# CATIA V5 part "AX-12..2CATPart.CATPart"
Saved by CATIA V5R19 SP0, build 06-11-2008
Part number: DX124_DUMMY
Revision: 27
Definition: design
Nomenclature: DX124_DUMMY
Source: made
Description: NOT SPECIFIED
Bounding box of the stored display mesh (mm): x -16 to 16, y -38.5 to 11.5, z -19 to 19
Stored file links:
  I:\mediator\AX-12..2CATPart.CATPart
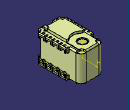
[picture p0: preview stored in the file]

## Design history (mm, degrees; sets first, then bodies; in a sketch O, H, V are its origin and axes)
Set1
  DatumSurface1 "CURVE_BOUNDED_SURFACE #7207"
  DatumSurface2 "CURVE_BOUNDED_SURFACE #7250"
  DatumSurface3 "CURVE_BOUNDED_SURFACE #7292"
  DatumSurface4 "CURVE_BOUNDED_SURFACE #7334"
  DatumSurface5 "CURVE_BOUNDED_SURFACE #7375"
  DatumSurface6 "CURVE_BOUNDED_SURFACE #7451"
  DatumSurface7 "CURVE_BOUNDED_SURFACE #7526"
  DatumSurface8 "CURVE_BOUNDED_SURFACE #7737"
  DatumSurface9 "CURVE_BOUNDED_SURFACE #7833"
  DatumSurface10 "CURVE_BOUNDED_SURFACE #7875"
  DatumSurface11 "CURVE_BOUNDED_SURFACE #7970"
  DatumSurface12 "CURVE_BOUNDED_SURFACE #8046"
  DatumSurface13 "CURVE_BOUNDED_SURFACE #8088"
  DatumSurface14 "CURVE_BOUNDED_SURFACE #8129"
  DatumSurface15 "CURVE_BOUNDED_SURFACE #8204"
  DatumSurface16 "CURVE_BOUNDED_SURFACE #8245"
  DatumSurface17 "CURVE_BOUNDED_SURFACE #8286"
  DatumSurface18 "CURVE_BOUNDED_SURFACE #8361"
  DatumSurface19 "CURVE_BOUNDED_SURFACE #9345"
  DatumSurface20 "CURVE_BOUNDED_SURFACE #9397"
  DatumSurface21 "CURVE_BOUNDED_SURFACE #9488"
  DatumSurface22 "CURVE_BOUNDED_SURFACE #9579"
  DatumSurface23 "CURVE_BOUNDED_SURFACE #9670"
  DatumSurface24 "CURVE_BOUNDED_SURFACE #9761"
  DatumSurface25 "CURVE_BOUNDED_SURFACE #9851"
  DatumSurface26 "CURVE_BOUNDED_SURFACE #9929"
  DatumSurface27 "CURVE_BOUNDED_SURFACE #10008"
  DatumSurface28 "CURVE_BOUNDED_SURFACE #10058"
  DatumSurface29 "CURVE_BOUNDED_SURFACE #10131"
  DatumSurface30 "CURVE_BOUNDED_SURFACE #10210"
  DatumSurface31 "CURVE_BOUNDED_SURFACE #10289"
  DatumSurface32 "CURVE_BOUNDED_SURFACE #10368"
  DatumSurface33 "CURVE_BOUNDED_SURFACE #10429"
  DatumSurface34 "CURVE_BOUNDED_SURFACE #10500"
  DatumSurface35 "CURVE_BOUNDED_SURFACE #10573"
  DatumSurface36 "CURVE_BOUNDED_SURFACE #10652"
  DatumSurface37 "CURVE_BOUNDED_SURFACE #10731"
  DatumSurface38 "CURVE_BOUNDED_SURFACE #10810"
  DatumSurface39 "CURVE_BOUNDED_SURFACE #10871"
  DatumSurface40 "CURVE_BOUNDED_SURFACE #10943"
  DatumSurface41 "CURVE_BOUNDED_SURFACE #10985"
  DatumSurface42 "CURVE_BOUNDED_SURFACE #11027"
  DatumSurface43 "CURVE_BOUNDED_SURFACE #11077"
  DatumSurface44 "CURVE_BOUNDED_SURFACE #11153"
  DatumSurface45 "CURVE_BOUNDED_SURFACE #11230"
  DatumSurface46 "CURVE_BOUNDED_SURFACE #11307"
  DatumSurface47 "CURVE_BOUNDED_SURFACE #11384"
  DatumSurface48 "CURVE_BOUNDED_SURFACE #11460"
  DatumSurface49 "CURVE_BOUNDED_SURFACE #11958"
  DatumSurface50 "CURVE_BOUNDED_SURFACE #12121"
  DatumSurface51 "CURVE_BOUNDED_SURFACE #12250"
  DatumSurface52 "CURVE_BOUNDED_SURFACE #12382"
  DatumSurface53 "CURVE_BOUNDED_SURFACE #12492"
  DatumSurface54 "CURVE_BOUNDED_SURFACE #12532"
  DatumSurface55 "CURVE_BOUNDED_SURFACE #12571"
  DatumSurface56 "CURVE_BOUNDED_SURFACE #12683"
  DatumSurface57 "CURVE_BOUNDED_SURFACE #12743"
  DatumSurface58 "CURVE_BOUNDED_SURFACE #12800"
  DatumSurface59 "CURVE_BOUNDED_SURFACE #12871"
  DatumSurface60 "CURVE_BOUNDED_SURFACE #12949"
  DatumSurface61 "CURVE_BOUNDED_SURFACE #13027"
  DatumSurface62 "CURVE_BOUNDED_SURFACE #13105"
  DatumSurface63 "CURVE_BOUNDED_SURFACE #13165"
  DatumSurface64 "CURVE_BOUNDED_SURFACE #13236"
  DatumSurface65 "CURVE_BOUNDED_SURFACE #13309"
  DatumSurface66 "CURVE_BOUNDED_SURFACE #13388"
  DatumSurface67 "CURVE_BOUNDED_SURFACE #13467"
  DatumSurface68 "CURVE_BOUNDED_SURFACE #13546"
  DatumSurface69 "CURVE_BOUNDED_SURFACE #13607"
  DatumSurface70 "CURVE_BOUNDED_SURFACE #13679"
  DatumSurface71 "CURVE_BOUNDED_SURFACE #13721"
  DatumSurface72 "CURVE_BOUNDED_SURFACE #13761"
  DatumSurface73 "CURVE_BOUNDED_SURFACE #13812"
  DatumSurface74 "CURVE_BOUNDED_SURFACE #13888"
  DatumSurface75 "CURVE_BOUNDED_SURFACE #13965"
  DatumSurface76 "CURVE_BOUNDED_SURFACE #14042"
  DatumSurface77 "CURVE_BOUNDED_SURFACE #14119"
  DatumSurface78 "CURVE_BOUNDED_SURFACE #14208"
  DatumSurface79 "CURVE_BOUNDED_SURFACE #14298"
  DatumSurface80 "CURVE_BOUNDED_SURFACE #14388"
  DatumSurface81 "CURVE_BOUNDED_SURFACE #14478"
  DatumSurface82 "CURVE_BOUNDED_SURFACE #14568"
  DatumSurface83 "CURVE_BOUNDED_SURFACE #14617"
  DatumSurface84 "CURVE_BOUNDED_SURFACE #14690"
  DatumSurface85 "CURVE_BOUNDED_SURFACE #14765"
  DatumSurface86 "CURVE_BOUNDED_SURFACE #14840"
  DatumSurface87 "CURVE_BOUNDED_SURFACE #14915"
  DatumSurface88 "CURVE_BOUNDED_SURFACE #14989"
  DatumSurface89 "CURVE_BOUNDED_SURFACE #15029"
  DatumSurface90 "CURVE_BOUNDED_SURFACE #15068"
  DatumSurface91 "CURVE_BOUNDED_SURFACE #15118"
  DatumSurface92 "CURVE_BOUNDED_SURFACE #15170"
  DatumSurface93 "CURVE_BOUNDED_SURFACE #15199"
  DatumSurface94 "CURVE_BOUNDED_SURFACE #15229"
  DatumSurface95 "CURVE_BOUNDED_SURFACE #15259"
  DatumSurface96 "CURVE_BOUNDED_SURFACE #15289"
  DatumSurface97 "CURVE_BOUNDED_SURFACE #15320"
  DatumSurface98 "CURVE_BOUNDED_SURFACE #15369"
  DatumSurface99 "CURVE_BOUNDED_SURFACE #15421"
  DatumSurface100 "CURVE_BOUNDED_SURFACE #15471"
  DatumSurface101 "CURVE_BOUNDED_SURFACE #16436"
  DatumSurface102 "CURVE_BOUNDED_SURFACE #16487"
  DatumSurface103 "CURVE_BOUNDED_SURFACE #16536"
  DatumSurface104 "CURVE_BOUNDED_SURFACE #16585"
  DatumSurface105 "CURVE_BOUNDED_SURFACE #16636"
  DatumSurface106 "CURVE_BOUNDED_SURFACE #16685"
  DatumSurface107 "CURVE_BOUNDED_SURFACE #16734"
  DatumSurface108 "CURVE_BOUNDED_SURFACE #16783"
  DatumSurface109 "CURVE_BOUNDED_SURFACE #16834"
  DatumSurface110 "CURVE_BOUNDED_SURFACE #16887"
  DatumSurface111 "CURVE_BOUNDED_SURFACE #16940"
  DatumSurface112 "CURVE_BOUNDED_SURFACE #16992"
  DatumSurface113 "CURVE_BOUNDED_SURFACE #17083"
  DatumSurface114 "CURVE_BOUNDED_SURFACE #17174"
  DatumSurface115 "CURVE_BOUNDED_SURFACE #17265"
  DatumSurface116 "CURVE_BOUNDED_SURFACE #17355"
  DatumSurface117 "CURVE_BOUNDED_SURFACE #17446"
  DatumSurface118 "CURVE_BOUNDED_SURFACE #17522"
  DatumSurface119 "CURVE_BOUNDED_SURFACE #17598"
  DatumSurface120 "CURVE_BOUNDED_SURFACE #17674"
  DatumSurface121 "CURVE_BOUNDED_SURFACE #17750"
  DatumSurface122 "CURVE_BOUNDED_SURFACE #17799"
  DatumSurface123 "CURVE_BOUNDED_SURFACE #17840"
  DatumSurface124 "CURVE_BOUNDED_SURFACE #17915"
  DatumSurface125 "CURVE_BOUNDED_SURFACE #17992"
  DatumSurface126 "CURVE_BOUNDED_SURFACE #18069"
  DatumSurface127 "CURVE_BOUNDED_SURFACE #18146"
  DatumSurface128 "CURVE_BOUNDED_SURFACE #18221"
  DatumSurface129 "CURVE_BOUNDED_SURFACE #18714"
  DatumSurface130 "CURVE_BOUNDED_SURFACE #18789"
  DatumSurface131 "CURVE_BOUNDED_SURFACE #18864"
  DatumSurface132 "CURVE_BOUNDED_SURFACE #18939"
  DatumSurface133 "CURVE_BOUNDED_SURFACE #19014"
  DatumSurface134 "CURVE_BOUNDED_SURFACE #19089"
  DatumSurface135 "CURVE_BOUNDED_SURFACE #19139"
  DatumSurface136 "CURVE_BOUNDED_SURFACE #19215"
  DatumSurface137 "CURVE_BOUNDED_SURFACE #19292"
  DatumSurface138 "CURVE_BOUNDED_SURFACE #19369"
  DatumSurface139 "CURVE_BOUNDED_SURFACE #19446"
  DatumSurface140 "CURVE_BOUNDED_SURFACE #19536"
  DatumSurface141 "CURVE_BOUNDED_SURFACE #19625"
  DatumSurface142 "CURVE_BOUNDED_SURFACE #19715"
  DatumSurface143 "CURVE_BOUNDED_SURFACE #19805"
  DatumSurface144 "CURVE_BOUNDED_SURFACE #19895"
  DatumSurface145 "CURVE_BOUNDED_SURFACE #19943"
  DatumSurface146 "CURVE_BOUNDED_SURFACE #19983"
  DatumSurface147 "CURVE_BOUNDED_SURFACE #20023"
  DatumSurface148 "CURVE_BOUNDED_SURFACE #20128"
  DatumSurface149 "CURVE_BOUNDED_SURFACE #20168"
  DatumSurface150 "CURVE_BOUNDED_SURFACE #20208"
  DatumSurface151 "CURVE_BOUNDED_SURFACE #20256"
  DatumSurface152 "CURVE_BOUNDED_SURFACE #20330"
  DatumSurface153 "CURVE_BOUNDED_SURFACE #20404"
  DatumSurface154 "CURVE_BOUNDED_SURFACE #20444"
  DatumSurface155 "CURVE_BOUNDED_SURFACE #20502"
  DatumSurface156 "CURVE_BOUNDED_SURFACE #20559"
  DatumSurface157 "CURVE_BOUNDED_SURFACE #20598"
  DatumSurface158 "CURVE_BOUNDED_SURFACE #20639"
  DatumSurface159 "CURVE_BOUNDED_SURFACE #20680"
  DatumSurface160 "CURVE_BOUNDED_SURFACE #20730"
  DatumSurface161 "CURVE_BOUNDED_SURFACE #20769"
  DatumSurface162 "CURVE_BOUNDED_SURFACE #20819"
  DatumSurface163 "CURVE_BOUNDED_SURFACE #20858"
  DatumSurface164 "CURVE_BOUNDED_SURFACE #20906"
  DatumSurface165 "CURVE_BOUNDED_SURFACE #20946"
  DatumSurface166 "CURVE_BOUNDED_SURFACE #20985"
  DatumSurface167 "CURVE_BOUNDED_SURFACE #21043"
  DatumSurface168 "CURVE_BOUNDED_SURFACE #21101"
  DatumSurface169 "CURVE_BOUNDED_SURFACE #21153"
  DatumSurface170 "CURVE_BOUNDED_SURFACE #21311"
  DatumSurface171 "CURVE_BOUNDED_SURFACE #21352"
  DatumSurface172 "CURVE_BOUNDED_SURFACE #21394"
  DatumSurface173 "CURVE_BOUNDED_SURFACE #21435"
  DatumSurface174 "CURVE_BOUNDED_SURFACE #21486"
  DatumSurface175 "CURVE_BOUNDED_SURFACE #21542"
  DatumSurface176 "CURVE_BOUNDED_SURFACE #21599"
  DatumSurface177 "CURVE_BOUNDED_SURFACE #21639"
  DatumSurface178 "CURVE_BOUNDED_SURFACE #21696"
  DatumSurface179 "CURVE_BOUNDED_SURFACE #21754"
  DatumSurface180 "CURVE_BOUNDED_SURFACE #21795"
  DatumSurface181 "CURVE_BOUNDED_SURFACE #21852"
  DatumSurface182 "CURVE_BOUNDED_SURFACE #21910"
  DatumSurface183 "CURVE_BOUNDED_SURFACE #21950"
  DatumSurface184 "CURVE_BOUNDED_SURFACE #22007"
  DatumSurface185 "CURVE_BOUNDED_SURFACE #22065"
  DatumSurface186 "CURVE_BOUNDED_SURFACE #22106"
  DatumSurface187 "CURVE_BOUNDED_SURFACE #22163"
  DatumSurface188 "CURVE_BOUNDED_SURFACE #22221"
  DatumSurface189 "CURVE_BOUNDED_SURFACE #22261"
  DatumSurface190 "CURVE_BOUNDED_SURFACE #22318"
  DatumSurface191 "CURVE_BOUNDED_SURFACE #22376"
  DatumSurface192 "CURVE_BOUNDED_SURFACE #22417"
  DatumSurface193 "CURVE_BOUNDED_SURFACE #22474"
  DatumSurface194 "CURVE_BOUNDED_SURFACE #22532"
  DatumSurface195 "CURVE_BOUNDED_SURFACE #22572"
  DatumSurface196 "CURVE_BOUNDED_SURFACE #22630"
  DatumSurface197 "CURVE_BOUNDED_SURFACE #22689"
  DatumSurface198 "CURVE_BOUNDED_SURFACE #22746"
  DatumSurface199 "CURVE_BOUNDED_SURFACE #22804"
  DatumSurface200 "CURVE_BOUNDED_SURFACE #22845"
  DatumSurface201 "CURVE_BOUNDED_SURFACE #22907"
  DatumSurface202 "CURVE_BOUNDED_SURFACE #22955"
  DatumSurface203 "CURVE_BOUNDED_SURFACE #23044"
  DatumSurface204 "CURVE_BOUNDED_SURFACE #23111"
  DatumSurface205 "CURVE_BOUNDED_SURFACE #23158"
  DatumSurface206 "CURVE_BOUNDED_SURFACE #23205"
  DatumSurface207 "CURVE_BOUNDED_SURFACE #23259"
  DatumSurface208 "CURVE_BOUNDED_SURFACE #23314"
  DatumSurface209 "CURVE_BOUNDED_SURFACE #23383"
  DatumSurface210 "CURVE_BOUNDED_SURFACE #23505"
  DatumSurface211 "CURVE_BOUNDED_SURFACE #23547"
  DatumSurface212 "CURVE_BOUNDED_SURFACE #23589"
  DatumSurface213 "CURVE_BOUNDED_SURFACE #23647"
  DatumSurface214 "CURVE_BOUNDED_SURFACE #23827"
  DatumSurface215 "CURVE_BOUNDED_SURFACE #23877"
  DatumSurface216 "CURVE_BOUNDED_SURFACE #23932"
  DatumSurface217 "CURVE_BOUNDED_SURFACE #23980"
  DatumSurface218 "CURVE_BOUNDED_SURFACE #24042"
  DatumSurface219 "CURVE_BOUNDED_SURFACE #24131"
  DatumSurface220 "CURVE_BOUNDED_SURFACE #24179"
  DatumSurface221 "CURVE_BOUNDED_SURFACE #24241"
  DatumSurface222 "CURVE_BOUNDED_SURFACE #24281"
  DatumSurface223 "CURVE_BOUNDED_SURFACE #24322"
  DatumSurface224 "CURVE_BOUNDED_SURFACE #24361"
  DatumSurface225 "CURVE_BOUNDED_SURFACE #24401"
  DatumSurface226 "CURVE_BOUNDED_SURFACE #24462"
  DatumSurface227 "CURVE_BOUNDED_SURFACE #24510"
  DatumSurface228 "CURVE_BOUNDED_SURFACE #24595"
  DatumSurface229 "CURVE_BOUNDED_SURFACE #24660"
  DatumSurface230 "CURVE_BOUNDED_SURFACE #24717"
  DatumSurface231 "CURVE_BOUNDED_SURFACE #24765"
  DatumSurface232 "CURVE_BOUNDED_SURFACE #24849"
  DatumSurface233 "CURVE_BOUNDED_SURFACE #24897"
  DatumSurface234 "CURVE_BOUNDED_SURFACE #24959"
  DatumSurface235 "CURVE_BOUNDED_SURFACE #24999"
  DatumSurface236 "CURVE_BOUNDED_SURFACE #25038"
  DatumSurface237 "CURVE_BOUNDED_SURFACE #25077"
  DatumSurface238 "CURVE_BOUNDED_SURFACE #25131"
  DatumSurface239 "CURVE_BOUNDED_SURFACE #25179"
  DatumSurface240 "CURVE_BOUNDED_SURFACE #25241"
  DatumSurface241 "CURVE_BOUNDED_SURFACE #25296"
  DatumSurface242 "CURVE_BOUNDED_SURFACE #25343"
  DatumSurface243 "CURVE_BOUNDED_SURFACE #27073"
  DatumSurface244 "CURVE_BOUNDED_SURFACE #27139"
  DatumSurface245 "CURVE_BOUNDED_SURFACE #27179"
  DatumSurface246 "CURVE_BOUNDED_SURFACE #27244"
  DatumSurface247 "CURVE_BOUNDED_SURFACE #27284"
  DatumSurface248 "CURVE_BOUNDED_SURFACE #27343"
  DatumSurface249 "CURVE_BOUNDED_SURFACE #27400"
  DatumSurface250 "CURVE_BOUNDED_SURFACE #27441"
  DatumSurface251 "CURVE_BOUNDED_SURFACE #27499"
  DatumSurface252 "CURVE_BOUNDED_SURFACE #27557"
  DatumSurface253 "CURVE_BOUNDED_SURFACE #27598"
  DatumSurface254 "CURVE_BOUNDED_SURFACE #27656"
  DatumSurface255 "CURVE_BOUNDED_SURFACE #27714"
  DatumSurface256 "CURVE_BOUNDED_SURFACE #27755"
  DatumSurface257 "CURVE_BOUNDED_SURFACE #27813"
  DatumSurface258 "CURVE_BOUNDED_SURFACE #27871"
  DatumSurface259 "CURVE_BOUNDED_SURFACE #27912"
  DatumSurface260 "CURVE_BOUNDED_SURFACE #27970"
  DatumSurface261 "CURVE_BOUNDED_SURFACE #28028"
  DatumSurface262 "CURVE_BOUNDED_SURFACE #28069"
  DatumSurface263 "CURVE_BOUNDED_SURFACE #28127"
  DatumSurface264 "CURVE_BOUNDED_SURFACE #28185"
  DatumSurface265 "CURVE_BOUNDED_SURFACE #28226"
  DatumSurface266 "CURVE_BOUNDED_SURFACE #28284"
  DatumSurface267 "CURVE_BOUNDED_SURFACE #28342"
  DatumSurface268 "CURVE_BOUNDED_SURFACE #28393"
  DatumSurface269 "CURVE_BOUNDED_SURFACE #28433"
  DatumSurface270 "CURVE_BOUNDED_SURFACE #28472"
  DatumSurface271 "CURVE_BOUNDED_SURFACE #28513"
  DatumSurface272 "CURVE_BOUNDED_SURFACE #28563"
  DatumSurface273 "CURVE_BOUNDED_SURFACE #28602"
  DatumSurface274 "CURVE_BOUNDED_SURFACE #28674"
  DatumSurface275 "CURVE_BOUNDED_SURFACE #28747"
  DatumSurface276 "CURVE_BOUNDED_SURFACE #28820"
  DatumSurface277 "CURVE_BOUNDED_SURFACE #28894"
  DatumSurface278 "CURVE_BOUNDED_SURFACE #28942"
  DatumSurface279 "CURVE_BOUNDED_SURFACE #28982"
  DatumSurface280 "CURVE_BOUNDED_SURFACE #29021"
  DatumSurface281 "CURVE_BOUNDED_SURFACE #29069"
  DatumSurface282 "CURVE_BOUNDED_SURFACE #29109"
  DatumSurface283 "CURVE_BOUNDED_SURFACE #29149"
  DatumSurface284 "CURVE_BOUNDED_SURFACE #29196"
  DatumSurface285 "CURVE_BOUNDED_SURFACE #29244"
  DatumSurface286 "CURVE_BOUNDED_SURFACE #29284"
  DatumSurface287 "CURVE_BOUNDED_SURFACE #29324"
  DatumSurface288 "CURVE_BOUNDED_SURFACE #29371"
  DatumSurface289 "CURVE_BOUNDED_SURFACE #29419"
  DatumSurface290 "CURVE_BOUNDED_SURFACE #29459"
  DatumSurface291 "CURVE_BOUNDED_SURFACE #29499"
  DatumSurface292 "CURVE_BOUNDED_SURFACE #29546"
  DatumSurface293 "CURVE_BOUNDED_SURFACE #29585"
  DatumSurface294 "CURVE_BOUNDED_SURFACE #29624"
  DatumSurface295 "CURVE_BOUNDED_SURFACE #29663"
  DatumSurface296 "CURVE_BOUNDED_SURFACE #29703"
  DatumSurface297 "CURVE_BOUNDED_SURFACE #29742"
  DatumSurface298 "CURVE_BOUNDED_SURFACE #29781"
  DatumSurface299 "CURVE_BOUNDED_SURFACE #29820"
  DatumSurface300 "CURVE_BOUNDED_SURFACE #29860"
  DatumSurface301 "CURVE_BOUNDED_SURFACE #29899"
  DatumSurface302 "CURVE_BOUNDED_SURFACE #29938"
  DatumSurface303 "CURVE_BOUNDED_SURFACE #29977"
  DatumSurface304 "CURVE_BOUNDED_SURFACE #30017"
  DatumSurface305 "CURVE_BOUNDED_SURFACE #30056"
  DatumSurface306 "CURVE_BOUNDED_SURFACE #30095"
  DatumSurface307 "CURVE_BOUNDED_SURFACE #30134"
  DatumSurface308 "CURVE_BOUNDED_SURFACE #30174"
  DatumSurface309 "CURVE_BOUNDED_SURFACE #30213"
  DatumSurface310 "CURVE_BOUNDED_SURFACE #30252"
  DatumSurface311 "CURVE_BOUNDED_SURFACE #30291"
  DatumSurface312 "CURVE_BOUNDED_SURFACE #30331"
  DatumSurface313 "CURVE_BOUNDED_SURFACE #30370"
  DatumSurface314 "CURVE_BOUNDED_SURFACE #30409"
  DatumSurface315 "CURVE_BOUNDED_SURFACE #30448"
  DatumSurface316 "CURVE_BOUNDED_SURFACE #30488"
  DatumSurface317 "CURVE_BOUNDED_SURFACE #30527"
  DatumSurface318 "CURVE_BOUNDED_SURFACE #30566"
  DatumSurface319 "CURVE_BOUNDED_SURFACE #30615"
  DatumSurface320 "CURVE_BOUNDED_SURFACE #30654"
  DatumSurface321 "CURVE_BOUNDED_SURFACE #30705"
  DatumSurface322 "CURVE_BOUNDED_SURFACE #30745"
  DatumSurface323 "CURVE_BOUNDED_SURFACE #30785"
  DatumSurface324 "CURVE_BOUNDED_SURFACE #30824"
  DatumSurface325 "CURVE_BOUNDED_SURFACE #30863"
  DatumSurface326 "CURVE_BOUNDED_SURFACE #30903"
  DatumSurface327 "CURVE_BOUNDED_SURFACE #30960"
  DatumSurface328 "CURVE_BOUNDED_SURFACE #31016"
  DatumSurface329 "CURVE_BOUNDED_SURFACE #31055"
  DatumSurface330 "CURVE_BOUNDED_SURFACE #31094"
  DatumSurface331 "CURVE_BOUNDED_SURFACE #31133"
  DatumSurface332 "CURVE_BOUNDED_SURFACE #31181"
  DatumSurface333 "CURVE_BOUNDED_SURFACE #31221"
  DatumSurface334 "CURVE_BOUNDED_SURFACE #31260"
  DatumSurface335 "CURVE_BOUNDED_SURFACE #31308"
  DatumSurface336 "CURVE_BOUNDED_SURFACE #31348"
  DatumSurface337 "CURVE_BOUNDED_SURFACE #31388"
  DatumSurface338 "CURVE_BOUNDED_SURFACE #31435"
  DatumSurface339 "CURVE_BOUNDED_SURFACE #31483"
  DatumSurface340 "CURVE_BOUNDED_SURFACE #31523"
  DatumSurface341 "CURVE_BOUNDED_SURFACE #31563"
  DatumSurface342 "CURVE_BOUNDED_SURFACE #31610"
  DatumSurface343 "CURVE_BOUNDED_SURFACE #31658"
  DatumSurface344 "CURVE_BOUNDED_SURFACE #31698"
  DatumSurface345 "CURVE_BOUNDED_SURFACE #31738"
  DatumSurface346 "CURVE_BOUNDED_SURFACE #31785"
  DatumSurface347 "CURVE_BOUNDED_SURFACE #31836"
  DatumSurface348 "CURVE_BOUNDED_SURFACE #31886"
  DatumSurface349 "CURVE_BOUNDED_SURFACE #31935"
  DatumSurface350 "CURVE_BOUNDED_SURFACE #31965"
  DatumSurface351 "CURVE_BOUNDED_SURFACE #31995"
  DatumSurface352 "CURVE_BOUNDED_SURFACE #32025"
  DatumSurface353 "CURVE_BOUNDED_SURFACE #32054"
  DatumSurface354 "CURVE_BOUNDED_SURFACE #32085"
  DatumSurface355 "CURVE_BOUNDED_SURFACE #32134"
  DatumSurface356 "CURVE_BOUNDED_SURFACE #32185"
  DatumSurface357 "CURVE_BOUNDED_SURFACE #32234"
  DatumSurface358 "CURVE_BOUNDED_SURFACE #32283"
  DatumSurface359 "CURVE_BOUNDED_SURFACE #32334"
  DatumSurface360 "CURVE_BOUNDED_SURFACE #32383"
  DatumSurface361 "CURVE_BOUNDED_SURFACE #32432"
  DatumSurface362 "CURVE_BOUNDED_SURFACE #32483"
  DatumSurface363 "CURVE_BOUNDED_SURFACE #32532"
  DatumSurface364 "CURVE_BOUNDED_SURFACE #32585"
  DatumSurface365 "CURVE_BOUNDED_SURFACE #32640"
  DatumSurface366 "CURVE_BOUNDED_SURFACE #32689"
  DatumSurface367 "CURVE_BOUNDED_SURFACE #32739"
  DatumSurface368 "CURVE_BOUNDED_SURFACE #32788"
  DatumSurface369 "CURVE_BOUNDED_SURFACE #32818"
  DatumSurface370 "CURVE_BOUNDED_SURFACE #32848"
  DatumSurface371 "CURVE_BOUNDED_SURFACE #32878"
  DatumSurface372 "CURVE_BOUNDED_SURFACE #32907"
  DatumSurface373 "CURVE_BOUNDED_SURFACE #32938"
  DatumSurface374 "CURVE_BOUNDED_SURFACE #32987"
  DatumSurface375 "CURVE_BOUNDED_SURFACE #33038"
  DatumSurface376 "CURVE_BOUNDED_SURFACE #33087"
  DatumSurface377 "CURVE_BOUNDED_SURFACE #33136"
  DatumSurface378 "CURVE_BOUNDED_SURFACE #33187"
  DatumSurface379 "CURVE_BOUNDED_SURFACE #33236"
  DatumSurface380 "CURVE_BOUNDED_SURFACE #33285"
  DatumSurface381 "CURVE_BOUNDED_SURFACE #33336"
  DatumSurface382 "CURVE_BOUNDED_SURFACE #33385"
  DatumSurface383 "CURVE_BOUNDED_SURFACE #33438"
  DatumSurface384 "CURVE_BOUNDED_SURFACE #33493"
  DatumSurface385 "CURVE_BOUNDED_SURFACE #33542"
  DatumSurface386 "CURVE_BOUNDED_SURFACE #33582"
  DatumSurface387 "CURVE_BOUNDED_SURFACE #33629"
  DatumSurface388 "CURVE_BOUNDED_SURFACE #33677"
  DatumSurface389 "CURVE_BOUNDED_SURFACE #33717"
  DatumSurface390 "CURVE_BOUNDED_SURFACE #33757"
  DatumSurface391 "CURVE_BOUNDED_SURFACE #33804"
  DatumSurface392 "CURVE_BOUNDED_SURFACE #33852"
  DatumSurface393 "CURVE_BOUNDED_SURFACE #33892"
  DatumSurface394 "CURVE_BOUNDED_SURFACE #33932"
  DatumSurface395 "CURVE_BOUNDED_SURFACE #33979"
  DatumSurface396 "CURVE_BOUNDED_SURFACE #34027"
  DatumSurface397 "CURVE_BOUNDED_SURFACE #34067"
  DatumSurface398 "CURVE_BOUNDED_SURFACE #34107"
  DatumSurface399 "CURVE_BOUNDED_SURFACE #34154"
  DatumSurface400 "CURVE_BOUNDED_SURFACE #34202"
  DatumSurface401 "CURVE_BOUNDED_SURFACE #34242"
  DatumSurface402 "CURVE_BOUNDED_SURFACE #34282"
  DatumSurface403 "CURVE_BOUNDED_SURFACE #34329"
  DatumSurface404 "CURVE_BOUNDED_SURFACE #34377"
  DatumSurface405 "CURVE_BOUNDED_SURFACE #34417"
  DatumSurface406 "CURVE_BOUNDED_SURFACE #34457"
  DatumSurface407 "CURVE_BOUNDED_SURFACE #34504"
  DatumSurface408 "CURVE_BOUNDED_SURFACE #34552"
  DatumSurface409 "CURVE_BOUNDED_SURFACE #34592"
  DatumSurface410 "CURVE_BOUNDED_SURFACE #34632"
  DatumSurface411 "CURVE_BOUNDED_SURFACE #34679"
  DatumSurface412 "CURVE_BOUNDED_SURFACE #34733"
  DatumSurface413 "CURVE_BOUNDED_SURFACE #34788"
  DatumSurface414 "CURVE_BOUNDED_SURFACE #34818"
  DatumSurface415 "CURVE_BOUNDED_SURFACE #34848"
  DatumSurface416 "CURVE_BOUNDED_SURFACE #34878"
  DatumSurface417 "CURVE_BOUNDED_SURFACE #34908"
  DatumSurface418 "CURVE_BOUNDED_SURFACE #34938"
  DatumSurface419 "CURVE_BOUNDED_SURFACE #34987"
  DatumSurface420 "CURVE_BOUNDED_SURFACE #35038"
  DatumSurface421 "CURVE_BOUNDED_SURFACE #35087"
  DatumSurface422 "CURVE_BOUNDED_SURFACE #35136"
  DatumSurface423 "CURVE_BOUNDED_SURFACE #35187"
  DatumSurface424 "CURVE_BOUNDED_SURFACE #35236"
  DatumSurface425 "CURVE_BOUNDED_SURFACE #35285"
  DatumSurface426 "CURVE_BOUNDED_SURFACE #35336"
  DatumSurface427 "CURVE_BOUNDED_SURFACE #35385"
  DatumSurface428 "CURVE_BOUNDED_SURFACE #35434"
  DatumSurface429 "CURVE_BOUNDED_SURFACE #35483"
  DatumSurface430 "CURVE_BOUNDED_SURFACE #35532"
  DatumSurface431 "CURVE_BOUNDED_SURFACE #35587"
  DatumSurface432 "CURVE_BOUNDED_SURFACE #35627"
  DatumSurface433 "CURVE_BOUNDED_SURFACE #35675"
  DatumSurface434 "CURVE_BOUNDED_SURFACE #35750"
  DatumSurface435 "CURVE_BOUNDED_SURFACE #35799"
  DatumSurface436 "CURVE_BOUNDED_SURFACE #35847"
  DatumSurface437 "CURVE_BOUNDED_SURFACE #35921"
  DatumSurface438 "CURVE_BOUNDED_SURFACE #36011"
  DatumSurface439 "CURVE_BOUNDED_SURFACE #36051"
  DatumSurface440 "CURVE_BOUNDED_SURFACE #36091"
  DatumSurface441 "CURVE_BOUNDED_SURFACE #36131"
  DatumSurface442 "CURVE_BOUNDED_SURFACE #36170"
  DatumSurface443 "CURVE_BOUNDED_SURFACE #36211"
  DatumSurface444 "CURVE_BOUNDED_SURFACE #36258"
  DatumSurface445 "CURVE_BOUNDED_SURFACE #36344"
  DatumSurface446 "CURVE_BOUNDED_SURFACE #36444"
  DatumSurface447 "CURVE_BOUNDED_SURFACE #36496"
  DatumSurface448 "CURVE_BOUNDED_SURFACE #36546"
  DatumSurface449 "CURVE_BOUNDED_SURFACE #36829"
  DatumSurface450 "CURVE_BOUNDED_SURFACE #36884"
  DatumSurface451 "CURVE_BOUNDED_SURFACE #36923"
  DatumSurface452 "CURVE_BOUNDED_SURFACE #36997"
  DatumSurface453 "CURVE_BOUNDED_SURFACE #37037"
  DatumSurface454 "CURVE_BOUNDED_SURFACE #37077"
  DatumSurface455 "CURVE_BOUNDED_SURFACE #37117"
  DatumSurface456 "CURVE_BOUNDED_SURFACE #37157"
  DatumSurface457 "CURVE_BOUNDED_SURFACE #37196"
  DatumSurface458 "CURVE_BOUNDED_SURFACE #37235"
  DatumSurface459 "CURVE_BOUNDED_SURFACE #37274"
  Sketch1 on yz-plane, origin (0, 0, 0), H (0, 1, 0), V (0, 0, 1)
    axis line L1 (0, 28.822) -> (0, -24.9828)
    point P1 (0, 28.822)
    coincidence: P1 V
    vertical: L1 V
Body1 (main body)
  Sketch2 on DatumSurface214, origin (0, 0, 16.6), H (1, 0, 0), V (0, 1, 0)
    circle A1 centre (0, 0) radius 4.5
    reference projected arc E1 centre (0, 0) radius 4.5 from (4.5, 0) to (-4.5, 0) ccw from edge of DatumSurface214
    circle A2 centre (0, 0) radius 5.3852
    distance A1 E1 = 0
  Pad1: profile Sketch2, direction (0, 0, -1), length 1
